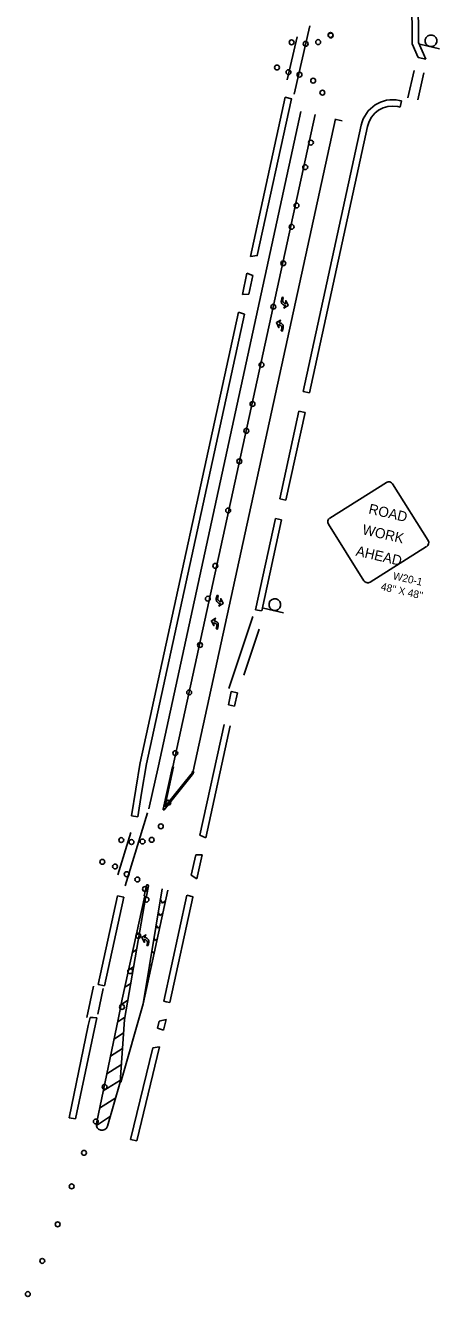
# Model space of a CAD drawing. Extents: x 1615924 to 1617091, y 899733 to 904714.
# Drawn here: x 1616178 to 1616506, y 899733 to 900741 of the extents above; entities that cross this region are included whole.
import ezdxf

# ---------------------------------------------------------------- set-up
doc = ezdxf.new("R2010")
doc.units = 0
for name, color, linetype in [('DEV PSS CELL', 7, 'Continuous'), ('Old_Level_20', 7, 'Continuous'), ('Prop Conc 2ft 6in Curb and Gutter', 7, 'Continuous'), ('Prop Conc 4in Sidewalk', 7, 'Continuous'), ('Prop Conc 5in Monolithic Keyed In Island', 7, 'Continuous'), ('Prop Conc Valley Gutter', 7, 'Continuous'), ('Prop Mkg 3ft Min Skp 3ft Wide White', 7, 'Continuous'), ('Prop Mkg Min Skp 6ft Yellow', 7, 'Continuous'), ('Prop Mkg Solid Double Yellow', 7, 'Continuous'), ('Prop Mkg Solid White Edge Line', 7, 'Continuous'), ('Prop Mkg Solid Yellow Diagonals', 7, 'Continuous'), ('Prop Mkg Solid Yellow Edge Line', 7, 'Continuous'), ('Scratch_Level_7', 7, 'Continuous'), ('Scratch_Level_8', 7, 'Continuous'), ('Stage 2 Barrells', 7, 'Continuous'), ('STAGE 3', 7, 'Continuous'), ('WS W20-1 CELL', 7, 'Continuous')]:
    doc.layers.add(name, color=color, linetype=linetype)

msp = doc.modelspace()

# ---------------------------------------------------------------- linework, layer by layer
at = {"layer": 'DEV PSS CELL'}
for p, q in [((1616490.4, 900726.4), (1616506.1, 900722.8)), ((1616366.7, 900279.1), (1616382.5, 900275.5))]:
    msp.add_line(p, q, dxfattribs=at)
for centre in [(1616499.3, 900729.1), (1616375.6, 900281.9)]:
    msp.add_arc(centre, 4.67, 260.0511, 256.8843, dxfattribs=at)
at = {"layer": 'Old_Level_20'}
for p, q in [((1616391, 900686.8), (1616403.4, 900741.1)), ((1616385.4, 900698.2), (1616393.2, 900732.3)), ((1616481.1, 900684), (1616486, 900705.7)), ((1616488.9, 900682.3), (1616493.8, 900703.8)), ((1616339.1, 900215.5), (1616358.1, 900272.6)), ((1616351, 900226), (1616363.2, 900262.4)), ((1616256.9, 900059), (1616274.8, 900116.9)), ((1616251.2, 900067.7), (1616261.6, 900101.3)), ((1616226.7, 899954.4), (1616231.9, 899979.3)), ((1616235.4, 899957.1), (1616239.7, 899977.5))]:
    msp.add_line(p, q, dxfattribs=at)
at = {"layer": 'Prop Conc 2ft 6in Curb and Gutter'}
for p, q in [((1616286.5, 900045.2), (1616284.8, 900048.2)), ((1616286.5, 900045.2), (1616289.2, 900047.3)), ((1616284.6, 900035.3), (1616283.2, 900037.9)), ((1616284.6, 900035.3), (1616287, 900037.2)), ((1616282.8, 900025.4), (1616281.5, 900027.7)), ((1616282.8, 900025.4), (1616284.7, 900027.1)), ((1616280.9, 900015.6), (1616279.8, 900017.4)), ((1616280.9, 900015.6), (1616282.5, 900016.9)), ((1616279, 900005.7), (1616278.1, 900007.2)), ((1616279, 900005.7), (1616280.3, 900006.8)), ((1616277.1, 899995.8), (1616276.5, 899996.9)), ((1616277.1, 899995.8), (1616278.1, 899996.6)), ((1616275.2, 899985.9), (1616274.8, 899986.7)), ((1616275.2, 899985.9), (1616275.9, 899986.5)), ((1616273.3, 899976.1), (1616273.1, 899976.5)), ((1616273.3, 899976.1), (1616273.7, 899976.3))]:
    msp.add_line(p, q, dxfattribs=at)
at = {"layer": 'Prop Conc 4in Sidewalk'}
for p, q in [((1616484.5, 900726.8), (1616483.2, 900841.3)), ((1616488.2, 900840.8), (1616489.5, 900727.9)), ((1616489.2, 900715.8), (1616484.5, 900726.8)), ((1616489.5, 900727.9), (1616495.2, 900714.5)), ((1616495.2, 900714.5), (1616489.2, 900715.8)), ((1616356.4, 900558.1), (1616383.9, 900684.3)), ((1616388.8, 900683.2), (1616361.7, 900558.8)), ((1616383.9, 900684.3), (1616388.8, 900683.2)), ((1616474.8, 900676.6), (1616473.2, 900676.9)), ((1616474.3, 900681.8), (1616475.9, 900681.5)), ((1616475.9, 900681.5), (1616474.8, 900676.6)), ((1616398.1, 900451.1), (1616444.1, 900662.3)), ((1616444.1, 900662.3), (1616398.1, 900451.1)), ((1616449, 900661.2), (1616403, 900450)), ((1616403, 900450), (1616449, 900661.2)), ((1616449, 900661.2), (1616403, 900450)), ((1616361.7, 900558.8), (1616356.4, 900558.1)), ((1616349.9, 900527.9), (1616353.5, 900544.7)), ((1616353.5, 900544.7), (1616358.3, 900543)), ((1616358.3, 900543), (1616355, 900528.1)), ((1616355, 900528.1), (1616349.9, 900527.9)), ((1616268.9, 900156.5), (1616346.8, 900513.8)), ((1616351.6, 900512.3), (1616273.9, 900155.7)), ((1616346.8, 900513.8), (1616351.6, 900512.3)), ((1616403, 900450), (1616398.1, 900451.1)), ((1616379.5, 900365.9), (1616394.7, 900435.4)), ((1616399.6, 900434.4), (1616384.4, 900364.8)), ((1616394.7, 900435.4), (1616399.6, 900434.4)), ((1616384.4, 900364.8), (1616379.5, 900365.9)), ((1616360.3, 900277.9), (1616376.1, 900350.3)), ((1616381, 900349.2), (1616365.2, 900276.9)), ((1616376.1, 900350.3), (1616381, 900349.2)), ((1616365.1, 900276.9), (1616360.3, 900277.9)), ((1616338.8, 900202.5), (1616341.1, 900213)), ((1616341.1, 900213), (1616346, 900211.9)), ((1616343.7, 900201.4), (1616338.8, 900202.5)), ((1616346, 900211.9), (1616343.7, 900201.4)), ((1616316.3, 900099.1), (1616335.4, 900186.9)), ((1616340.3, 900185.8), (1616321, 900097)), ((1616262, 900114.3), (1616269, 900156.7)), ((1616269, 900156.7), (1616268.9, 900156.5)), ((1616273.9, 900155.7), (1616270, 900132.5)), ((1616270, 900132.5), (1616267, 900113.5)), ((1616267, 900113.5), (1616262, 900114.3)), ((1616321, 900097), (1616316.3, 900099.1)), ((1616309.4, 900067.3), (1616312.9, 900083.4)), ((1616312.9, 900083.4), (1616318, 900083.4)), ((1616318, 900083.4), (1616313.9, 900064.4)), ((1616313.9, 900064.4), (1616309.4, 900067.3)), ((1616235.6, 899980.6), (1616251, 900050.9)), ((1616251, 900050.9), (1616255.9, 900049.8)), ((1616287.6, 899967.4), (1616305.9, 900051.4)), ((1616305.9, 900051.4), (1616310.8, 900050.1)), ((1616255.9, 900049.8), (1616240.5, 899979.6)), ((1616240.5, 899979.6), (1616235.6, 899980.6)), ((1616289.6, 899967), (1616287.6, 899967.4)), ((1616292.5, 899966.3), (1616289.6, 899967)), ((1616217.6, 899874), (1616234.6, 899954.2)), ((1616229.2, 899954.4), (1616227.7, 899948.2)), ((1616282.6, 899946.1), (1616283.9, 899951.6)), ((1616283.9, 899951.6), (1616289.4, 899952.9)), ((1616289.4, 899952.9), (1616287.3, 899944.3)), ((1616227.7, 899948.2), (1616212.7, 899875)), ((1616287.3, 899944.3), (1616282.6, 899946.1)), ((1616261.3, 899857.7), (1616278.8, 899930.3)), ((1616284.2, 899931.2), (1616266.2, 899856.6)), ((1616278.8, 899930.3), (1616284.2, 899931.2)), ((1616212.7, 899875), (1616217.6, 899874)), ((1616266.2, 899856.6), (1616261.3, 899857.7))]:
    msp.add_line(p, q, dxfattribs=at)
for points in [[(1616310.8, 900050.1), (1616310.7, 900049.8), (1616292.5, 899966.3)], [(1616234.6, 899954.2), (1616231.6, 899954.5), (1616231, 899954.5), (1616229.2, 899954.4)]]:
    msp.add_lwpolyline(points, dxfattribs=at)
for radius in [25.5, 20.5]:
    msp.add_arc((1616469, 900656.9), radius, 78.1493, 167.7098, dxfattribs=at)
at = {"layer": 'Prop Conc 5in Monolithic Keyed In Island'}
msp.add_line((1616294.8, 900153.3), (1616407.6, 900670.7), dxfattribs=at)
at = {"layer": 'Prop Conc Valley Gutter'}
for p, q in [((1616265.8, 900020), (1616268.5, 900021.7)), ((1616262.8, 900006.1), (1616266.1, 900008.3)), ((1616259.8, 899992.3), (1616263.8, 899994.9)), ((1616256.8, 899978.5), (1616261.5, 899981.5)), ((1616254, 899964.9), (1616259.2, 899968.2)), ((1616251.2, 899951.1), (1616256.8, 899954.8)), ((1616248.3, 899937.4), (1616255.8, 899942.2)), ((1616245.4, 899923.7), (1616254.9, 899929.8)), ((1616242.5, 899909.9), (1616254.1, 899917.3)), ((1616239.7, 899896.2), (1616253.2, 899904.9)), ((1616236.8, 899882.5), (1616249.5, 899890.7)), ((1616234.2, 899868.9), (1616245.4, 899876.1))]:
    msp.add_line(p, q, dxfattribs=at)
at = {"layer": 'Prop Mkg 3ft Min Skp 3ft Wide White'}
msp.add_line((1616311, 900149.8), (1616423.7, 900667.2), dxfattribs=at)
at = {"layer": 'Prop Mkg Min Skp 6ft Yellow'}
for points in [[(1616382.3, 900525.5), (1616381.3, 900525.7), (1616380.8, 900523.2), (1616380.7, 900522.7), (1616380.7, 900522.3), (1616380.7, 900521.9), (1616380.8, 900521.6), (1616380.9, 900521.3), (1616381.1, 900520.9), (1616381.3, 900520.6), (1616381.6, 900520.3), (1616381.9, 900520), (1616382.2, 900519.8), (1616382.6, 900519.6), (1616383.1, 900519.4), (1616383.9, 900519.2), (1616382.8, 900517.2), (1616386.1, 900519.1), (1616384.2, 900523.1), (1616384.2, 900520.8), (1616383.6, 900520.9), (1616383.2, 900521), (1616382.9, 900521.2), (1616382.7, 900521.4), (1616382.4, 900521.7), (1616382.2, 900521.9), (1616382, 900522.3), (1616381.9, 900522.7), (1616381.8, 900523.1), (1616381.9, 900523.6)], [(1616380.7, 900499.2), (1616381.7, 900499), (1616382.3, 900501.5), (1616382.3, 900502), (1616382.3, 900502.4), (1616382.3, 900502.8), (1616382.2, 900503.1), (1616382.1, 900503.4), (1616381.9, 900503.8), (1616381.7, 900504.1), (1616381.4, 900504.4), (1616381.1, 900504.7), (1616380.8, 900504.9), (1616380.4, 900505.1), (1616379.9, 900505.3), (1616379.1, 900505.5), (1616380.2, 900507.5), (1616376.9, 900505.6), (1616378.8, 900501.6), (1616378.8, 900503.9), (1616379.4, 900503.8), (1616379.8, 900503.7), (1616380.1, 900503.5), (1616380.3, 900503.3), (1616380.6, 900503), (1616380.8, 900502.8), (1616381, 900502.4), (1616381.1, 900502), (1616381.2, 900501.6), (1616381.1, 900501.1)], [(1616330.8, 900289.1), (1616329.8, 900289.3), (1616329.2, 900286.7), (1616329.2, 900286.3), (1616329.2, 900285.9), (1616329.2, 900285.5), (1616329.3, 900285.1), (1616329.4, 900284.9), (1616329.6, 900284.5), (1616329.8, 900284.2), (1616330.1, 900283.9), (1616330.4, 900283.6), (1616330.7, 900283.4), (1616331.1, 900283.2), (1616331.6, 900283), (1616332.4, 900282.8), (1616331.3, 900280.8), (1616334.6, 900282.7), (1616332.7, 900286.7), (1616332.7, 900284.4), (1616332.1, 900284.5), (1616331.7, 900284.6), (1616331.4, 900284.8), (1616331.2, 900285), (1616330.9, 900285.2), (1616330.7, 900285.5), (1616330.5, 900285.8), (1616330.4, 900286.3), (1616330.3, 900286.7), (1616330.4, 900287.2)], [(1616329.2, 900262.8), (1616330.2, 900262.6), (1616330.8, 900265.1), (1616330.8, 900265.6), (1616330.8, 900265.9), (1616330.8, 900266.3), (1616330.7, 900266.7), (1616330.6, 900267), (1616330.4, 900267.4), (1616330.2, 900267.6), (1616329.9, 900267.9), (1616329.6, 900268.3), (1616329.3, 900268.4), (1616328.9, 900268.7), (1616328.4, 900268.9), (1616327.6, 900269), (1616328.7, 900271.1), (1616325.4, 900269.2), (1616327.3, 900265.2), (1616327.3, 900267.5), (1616327.9, 900267.3), (1616328.3, 900267.2), (1616328.6, 900267.1), (1616328.8, 900266.9), (1616329.1, 900266.6), (1616329.3, 900266.4), (1616329.5, 900266), (1616329.6, 900265.6), (1616329.7, 900265.2), (1616329.6, 900264.7)]]:
    msp.add_lwpolyline(points, close=True, dxfattribs=at)
at = {"layer": 'Prop Mkg Solid Double Yellow'}
for p, q in [((1616254.7, 899969), (1616272.6, 900051)), ((1616273.5, 900050.8), (1616256.5, 899953)), ((1616251.8, 899954.2), (1616254.7, 899969)), ((1616234.3, 899870.4), (1616251.8, 899954.2)), ((1616256.5, 899952.9), (1616253.1, 899903.2)), ((1616243.1, 899868.2), (1616253.1, 899903.3))]:
    msp.add_line(p, q, dxfattribs=at)
msp.add_arc((1616238.7, 899869.5), 4.57, 168.1708, 344.0989, dxfattribs=at)
at = {"layer": 'Prop Mkg Solid White Edge Line'}
msp.add_line((1616283.3, 900154.2), (1616396.3, 900673.1), dxfattribs=at)
at = {"layer": 'Prop Mkg Solid Yellow Diagonals'}
msp.add_lwpolyline([(1616274.3, 900011.7), (1616275.2, 900011.6), (1616275.7, 900014.1), (1616275.7, 900014.6), (1616275.7, 900015), (1616275.7, 900015.4), (1616275.6, 900015.7), (1616275.4, 900016), (1616275.2, 900016.4), (1616275, 900016.6), (1616274.8, 900016.9), (1616274.4, 900017.2), (1616274.1, 900017.4), (1616273.7, 900017.6), (1616273.2, 900017.8), (1616272.4, 900017.9), (1616273.4, 900020), (1616270.2, 900017.9), (1616272.2, 900014), (1616272.1, 900016.3), (1616272.8, 900016.2), (1616273.1, 900016.1), (1616273.4, 900016), (1616273.7, 900015.8), (1616274, 900015.6), (1616274.2, 900015.3), (1616274.4, 900015), (1616274.5, 900014.6), (1616274.6, 900014.2), (1616274.6, 900013.6)], close=True, dxfattribs=at)
msp.add_lwpolyline([(1616274.3, 900011.7), (1616275.2, 900011.6), (1616275.7, 900014.1), (1616275.7, 900014.6), (1616275.7, 900015), (1616275.7, 900015.4), (1616275.6, 900015.7), (1616275.4, 900016), (1616275.2, 900016.4), (1616275, 900016.6), (1616274.8, 900016.9), (1616274.4, 900017.2), (1616274.1, 900017.4), (1616273.7, 900017.6), (1616273.2, 900017.8), (1616272.4, 900017.9), (1616273.4, 900020), (1616270.2, 900017.9), (1616272.2, 900014), (1616272.1, 900016.3), (1616272.8, 900016.2), (1616273.1, 900016.1), (1616273.4, 900016), (1616273.7, 900015.8), (1616274, 900015.6), (1616274.2, 900015.3), (1616274.4, 900015), (1616274.5, 900014.6), (1616274.6, 900014.2), (1616274.6, 900013.6)], close=True, dxfattribs=at)
at = {"layer": 'Prop Mkg Solid Yellow Edge Line'}
for p, q in [((1616429, 900665.6), (1616424.1, 900666.6)), ((1616287, 900119.6), (1616294.4, 900153.4)), ((1616288.4, 900121.5), (1616295.3, 900153.2)), ((1616287.9, 900119.2), (1616310.1, 900146.9)), ((1616288.4, 900121.5), (1616309.3, 900147.5)), ((1616273.8, 900059.2), (1616272.1, 900051.1)), ((1616275.5, 900058.9), (1616274, 900050.7))]:
    msp.add_line(p, q, dxfattribs=at)
for centre, radius, start, end in [((1616304.8, 900151.1), 5.8, 321.1993, 347.7098), ((1616304.8, 900151.1), 6.8, 321.1993, 347.7098), ((1616287.5, 900119.5), 0.5, 167.7098, 321.1993), ((1616274.6, 900059), 0.824, 350.0967, 167.7446)]:
    msp.add_arc(centre, radius, start, end, dxfattribs=at)
at = {"layer": 'Scratch_Level_7'}
for p, q in [((1616283.3, 900154.2), (1616275.8, 900120.1)), ((1616271.3, 899965.4), (1616286.2, 900056.5)), ((1616271.3, 899965.4), (1616290.9, 900055.5))]:
    msp.add_line(p, q, dxfattribs=at)
at = {"layer": 'Scratch_Level_8'}
msp.add_line((1616253.6, 899903.1), (1616271.3, 899965.4), dxfattribs=at)
at = {"layer": 'Stage 2 Barrells'}
for centre in [(1616388.9, 900727.9), (1616400, 900726.7), (1616409.9, 900728.1), (1616419.7, 900733.8), (1616419.9, 900733.3), (1616377.3, 900707.9), (1616386.4, 900704.3), (1616395.2, 900702.3), (1616406, 900697.5), (1616413.3, 900688), (1616404.2, 900648.4), (1616399.7, 900628.9), (1616392.8, 900598.5), (1616388.9, 900581.6), (1616382.3, 900552.6), (1616374.4, 900518.2), (1616365, 900472.2), (1616357.9, 900441.1), (1616353, 900419.8), (1616347.5, 900395.6), (1616338.6, 900356.6), (1616328.5, 900312.7), (1616322.5, 900286.6), (1616316.3, 900249.9), (1616307.7, 900212.3), (1616296.7, 900164.1), (1616291.2, 900124.9), (1616285.3, 900106.1), (1616253.9, 900095.2), (1616262, 900093.6), (1616270.8, 900094.1), (1616278, 900095.4), (1616238.9, 900077.9), (1616249, 900074.2), (1616258.2, 900068.1), (1616266.7, 900063.9), (1616272.7, 900056.4), (1616273.9, 900048), (1616267.4, 900019.3), (1616261, 899991.2), (1616254.5, 899962.8), (1616240.7, 899899.5), (1616233.8, 899872), (1616224.4, 899847.1), (1616214.6, 899820.5), (1616203.5, 899790.4), (1616191.3, 899761.4), (1616179.9, 899735.1)]:
    msp.add_circle(centre, 1.93, dxfattribs=at)
at = {"layer": 'STAGE 3'}
msp.add_lwpolyline([(1616356.4, 900558.1), (1616383.9, 900684.3), (1616388.8, 900683.2), (1616361.7, 900558.8)], close=True, dxfattribs=at)
at = {"layer": 'WS W20-1 CELL'}
msp.add_line((1616495.9, 900328), (1616451.1, 900299.8), dxfattribs=at)
for points in [[(1616419.2, 900350.6), (1616464.1, 900378.8)], [(1616468.9, 900377.7), (1616497, 900332.8)], [(1616446.2, 900300.9), (1616418.1, 900345.8)]]:
    msp.add_lwpolyline(points, dxfattribs=at)
for centre, start, end in [((1616465.9, 900375.8), 77.1019, 122.1084), ((1616465.9, 900375.8), 32.0954, 77.1019), ((1616421, 900347.7), 122.1084, 212.1084), ((1616494.1, 900330.9), 302.1084, 32.1084), ((1616449.2, 900302.8), 212.1084, 257.1084), ((1616449.2, 900302.8), 257.1084, 302.1084)]:
    msp.add_arc(centre, 3.5, start, end, dxfattribs=at)

# ---------------------------------------------------------------- texts
for s, height, p in [('ROAD', 8, (1616449.4, 900354.3)), ('WORK', 8, (1616444.4, 900337.9)), ('AHEAD', 8, (1616439.3, 900320.9)), ('W20-1', 6, (1616468.8, 900302.1)), ("48'' X 48''", 6, (1616459.2, 900293.6))]:
    msp.add_text(s, height=height, rotation=347.1084, dxfattribs=at).set_placement(p)

doc.saveas('drawing.dxf')
